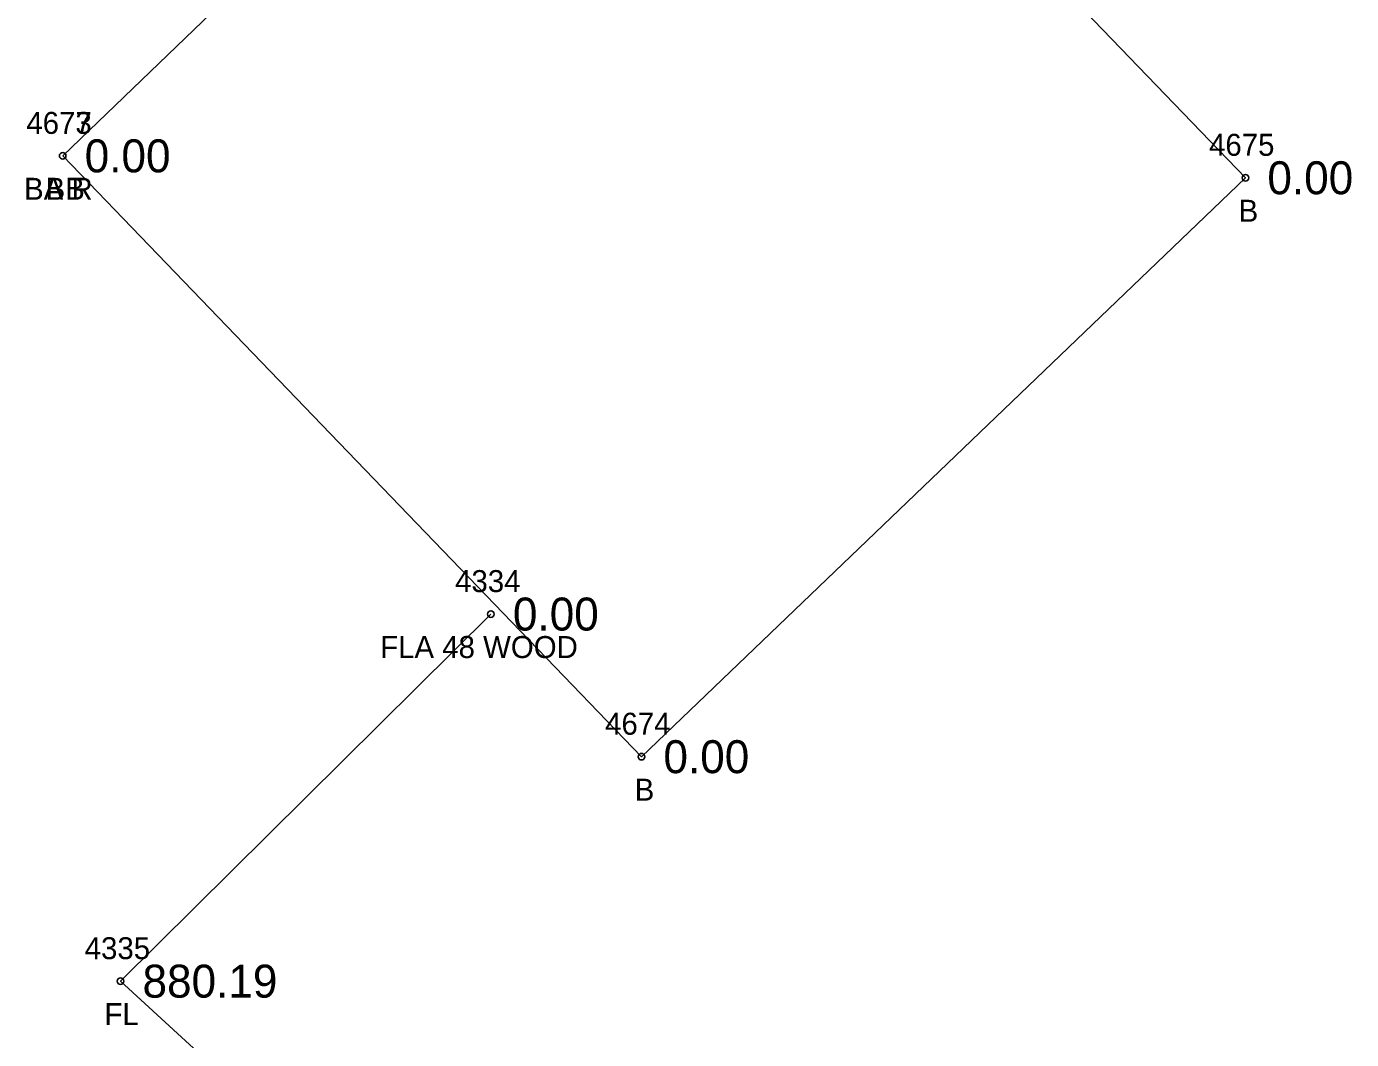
# Model space of a CAD drawing. Extents: x 1622501 to 1626664, y 1117816 to 1121579.
# Drawn here: x 1625414.5 to 1625474.7, y 1120722.8 to 1120768.9 of the extents above; entities that cross this region are included whole.
import ezdxf

# ---------------------------------------------------------------- set-up
doc = ezdxf.new("R2010")
doc.units = 0
for name, color, linetype in [('RD_EX_Bldg', 7, 'Continuous'), ('RD_EX_Bldg_txCode', 7, 'Continuous'), ('RD_EX_Fence_Other', 7, 'Continuous'), ('RD_EX_Fence_Other_txCode', 7, 'Continuous'), ('RD_EX_TX_Bldg_ELEV', 7, 'Continuous'), ('RD_EX_TX_Fence_Other_ELEV', 7, 'Continuous'), ('RD_SMD_Locator', 7, 'Continuous')]:
    doc.layers.add(name, color=color, linetype=linetype)

msp = doc.modelspace()

# ---------------------------------------------------------------- linework, layer by layer
at = {"layer": 'RD_EX_Bldg'}
msp.add_lwpolyline([(1625416.104, 1120763.024), (1625442.424, 1120735.683), (1625469.89, 1120762.026), (1625443.521, 1120789.417), (1625416.104, 1120763.024)], dxfattribs=at)
at = {"layer": 'RD_EX_Fence_Other'}
msp.add_lwpolyline([(1625435.579, 1120742.173), (1625418.734, 1120725.47), (1625437.576, 1120708.158), (1625453.545, 1120716.361), (1625468.822, 1120707.682)], dxfattribs=at)
at = {"layer": 'RD_SMD_Locator'}
for centre in [(1625416.104, 1120763.024), (1625416.104, 1120763.024), (1625469.89, 1120762.026), (1625435.579, 1120742.173), (1625442.424, 1120735.683), (1625418.734, 1120725.47)]:
    msp.add_circle(centre, 0.15, dxfattribs=at)

# ---------------------------------------------------------------- texts
at = {"layer": 'RD_EX_Bldg_txCode'}
for s, p in [('4673', (1625414.451, 1120764.024)), ('4677', (1625414.451, 1120764.024)), ('4675', (1625468.236, 1120763.026)), ('BA R', (1625414.348, 1120761.024)), ('BB', (1625415.325, 1120761.024)), ('B', (1625469.582, 1120760.026)), ('4674', (1625440.771, 1120736.683)), ('B', (1625442.117, 1120733.683))]:
    msp.add_text(s, height=1, dxfattribs=at).set_placement(p)
at = {"layer": 'RD_EX_Fence_Other_txCode'}
for s, p in [('4334', (1625433.949, 1120743.173)), ('FLA 48 WOOD', (1625430.54, 1120740.173)), ('4335', (1625417.104, 1120726.47)), ('FL', (1625418.001, 1120723.47))]:
    msp.add_text(s, height=1, dxfattribs=at).set_placement(p)
at = {"layer": 'RD_EX_TX_Bldg_ELEV'}
for p in [(1625417.104, 1120762.274), (1625417.104, 1120762.274), (1625470.89, 1120761.276), (1625443.424, 1120734.933)]:
    msp.add_text('0.00', height=1.5, dxfattribs=at).set_placement(p)
at = {"layer": 'RD_EX_TX_Fence_Other_ELEV'}
for s, p in [('0.00', (1625436.579, 1120741.423)), ('880.19', (1625419.734, 1120724.72))]:
    msp.add_text(s, height=1.5, dxfattribs=at).set_placement(p)

doc.saveas('drawing.dxf')
